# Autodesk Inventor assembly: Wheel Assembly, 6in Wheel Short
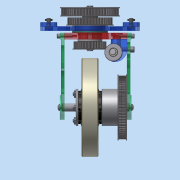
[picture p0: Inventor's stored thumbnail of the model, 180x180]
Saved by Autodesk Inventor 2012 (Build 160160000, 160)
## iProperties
Created: 2010-12
Part Number: Wheel Assembly, 6in Wheel Short
Document SubType Name: Assembly
Designer: PJ Suflita
Mass: 1486.61 g
Surface Area: 3664.62 cm^2
Volume: 597.184 cm^3
Density: 2.48936 g/cm^3
Author: PJ Suflita
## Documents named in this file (38)
- C:\Users\Owner\Documents\Robotics\Mechanical Design\DriveTrain2013 - post-season\Wheel Assembly\Inventor Parts\Wheel Assembly, 6in Wheel Short.iam
- C:\Users\Owner\Documents\Robotics\Mechanical Design\DriveTrain2013 - post-season\Wheel Assembly\Inventor Parts\SteeringRace_short.ipt
- C:\Users\Owner\Documents\Robotics\Mechanical Design\DriveTrain2013 - post-season\Wheel Assembly\Inventor Parts\ForkTopPlateLW.ipt
- C:\Users\Owner\Documents\Robotics\Mechanical Design\Parts\Bearings and Bushings\Thrust Bearings\Thrust Bearing, 1.500 in ID (INA TC2435).ipt
- C:\Users\Owner\Documents\Robotics\Mechanical Design\Parts\Bearings and Bushings\Thrust Bearings\Thrust Bearing Washer, 1.500 in ID (INA TWA2435).ipt
- C:\Users\Owner\Documents\Robotics\Mechanical Design\DriveTrain2013 - post-season\Wheel Assembly\Inventor Parts\AxleLWFinal.ipt
- C:\Users\Owner\Documents\Robotics\Mechanical Design\Parts\Wheels\2008-FIRST-Wheel\2008_FIRST-Wheel_Team174_Cleaned_up_version.iam
- C:\Users\Owner\Documents\Robotics\Mechanical Design\Parts\Fasteners\Retaining Rings (C-Clips)\Standard Retaining Ring, For 0.500 in Shaft (0.468 in Groove OD).ipt
- C:\Users\Owner\Documents\Robotics\Mechanical Design\Parts\Fasteners\Bolts and Screws\Socket Head Cap Screws - Buttonhead\SHCS (Buttonhead) - 1_4-20 UNC - UNC - 0.5(1).ipt
- C:\Users\Owner\Documents\Robotics\Mechanical Design\Parts\pulley\HTD\32\HTD 5mm 32 Tooth rev003 Assembly 001 step 4.iam
- C:\Users\Owner\Documents\Robotics\Mechanical Design\Parts\Bearings and Bushings\Roller Bearings\Roller Bearing, Flanged, 0.375 in ID.ipt
- C:\Users\Owner\Documents\Robotics\Mechanical Design\Parts\Fasteners\Shims\Washer, Spacer 0.375 in ID (0.020 in Thick).ipt
- C:\Users\Owner\Documents\Robotics\Mechanical Design\Parts\Fasteners\Retaining Rings (C-Clips)\Standard Retaining Ring, For 0.375 in Shaft (0.352 in Groove OD).ipt
- C:\Users\Owner\Documents\Robotics\Mechanical Design\Parts\Fasteners\Bolts and Screws\Socket Head Cap Screws\SHCS - 6-32 UNC - 0.5(31).ipt
- C:\Users\Owner\Documents\Robotics\Mechanical Design\Parts\Fasteners\Shims\Washer, Spacer 0.250 in ID (0.010 in Thick).ipt
- C:\Users\Owner\Documents\Robotics\Mechanical Design\Parts\Bearings and Bushings\Roller Bearings\Roller Bearing, Flanged, 0.250 in ID.ipt
- C:\Users\Owner\Documents\Robotics\Mechanical Design\Parts\pulley\HTD\16\HTD 5mm 16 Tooth rev001 Assembly.iam
- C:\Users\Owner\Documents\Robotics\Mechanical Design\DriveTrain2013 - post-season\Wheel Assembly\Inventor Parts\Customized Wheel Spacer.ipt
- C:\Users\Owner\Documents\Robotics\Mechanical Design\Parts\Bearings and Bushings\Roller Bearings\Roller Bearing, Flanged, 0.500 in ID.ipt
- C:\Users\Owner\Documents\Robotics\Mechanical Design\Parts\Fasteners\Shims\Washer, Spacer 0.500 in ID (0.020 in Thick).ipt
- C:\Users\Owner\Documents\Robotics\Mechanical Design\Parts\Fasteners\Bolts and Screws\Socket Head Cap Screws\SHCS - 10-32 UNF - 0.75(31).ipt
- C:\Users\Owner\Documents\Robotics\Mechanical Design\Parts\Fasteners\Bolts and Screws\Socket Head Cap Screws - Shoulder Bolt\SHCS, Shoulder, #10-32, 0.25 in Shoulder OD, 0.815 in Shoulder Length.ipt
- C:\Users\Owner\Documents\Robotics\Mechanical Design\Parts\pulley\HTD\56\HTD 5mm 56 Tooth Assembly rev003.iam
- C:\Users\Owner\Documents\Robotics\Mechanical Design\DriveTrain2013 - post-season\Wheel Assembly\Inventor Parts\Vertical Driven Shaft.ipt
- C:\Users\Owner\Documents\Robotics\Mechanical Design\Parts\pulley\HTD\44\HTD 5mm 44 Tooth rev001 Assembly 001.iam
- C:\Users\Owner\Documents\Robotics\Mechanical Design\Parts\pulley\HTD\9mm\Double Flange\62 Tooth\62 Tooth Complete Assembly.iam
- C:\Users\Owner\Documents\Robotics\Mechanical Design\Parts\Fasteners\Hexagon Nuts\Hex Nut, 8-32.ipt
- C:\Users\Owner\Documents\Robotics\Mechanical Design\DriveTrain2013 - post-season\Wheel Assembly\Inventor Parts\WheelWasher.ipt
- C:\Users\Owner\Documents\Robotics\Mechanical Design\Parts\Fasteners\Bolts and Screws\Socket Head Cap Screws\SHCS - 1_4-20 UNC - 0.75(31).ipt
- C:\Users\Owner\Documents\Robotics\Mechanical Design\Parts\8020 Hardware\8020 Single Slide-In Economy T-Nuts.ipt
- C:\Users\Owner\Documents\Robotics\Mechanical Design\DriveTrain2013 - post-season\Wheel Assembly\Inventor Parts\SteeringShaft_Short with Bushings.ipt
- C:\Users\Owner\Documents\Robotics\Mechanical Design\DriveTrain2013 - post-season\Wheel Assembly\Inventor Parts\FramePlateLW.ipt
- C:\Users\Owner\Documents\Robotics\Mechanical Design\Parts\Bearings and Bushings\Needle Bearings\Needle Bearing, 1.500 in ID (IKO BA248ZOH).ipt
- C:\Users\Owner\Documents\Robotics\Mechanical Design\DriveTrain2013 - post-season\Wheel Assembly\Inventor Parts\SideActiveFor6inWheel.ipt
- C:\Users\Owner\Documents\Robotics\Mechanical Design\DriveTrain2013 - post-season\Wheel Assembly\Inventor Parts\SidePassiveFor6inWheel.ipt
- C:\Users\Owner\Documents\Robotics\Mechanical Design\DriveTrain2013 - post-season\Wheel Assembly\Inventor Parts\Oblique Mount Block_Stationary_ForMachining.ipt
- C:\Users\Owner\Documents\Robotics\Mechanical Design\Parts\Fasteners\Bolts and Screws\Socket Head Cap Screws - Buttonhead\SHCS (Buttonhead) - 1_4-20 UNC - UNC - 0.75(1).ipt
- C:\Users\Owner\Documents\Inventor\Content Center Files\R2012\en-US\ANSI B18.3(05)\ANSI B18.3 - 8-32 UNC - 3(31).ipt
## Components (82 placed, 37 different names)
1. Washer, Spacer 0.375 in ID (0.020 in Thick):2 — Insert:118, Insert:155
2. HTD 5mm 56 Tooth Assembly rev003:2 [sub-assembly] — Insert:155, Angle:4
3. Roller Bearing, Flanged, 0.250 in ID:4 — Insert:126, Insert:127
4. HTD 5mm 44 Tooth rev001 Assembly 001:1 [sub-assembly] — Insert:159, Insert:163, Insert:179, Insert:180, Insert:194, Mate:177
5. Vertical Driven Shaft:1 — Insert:156, Insert:160, Insert:164
6. Standard Retaining Ring, For 0.375 in Shaft (0.352 in Groove OD):2 — Insert:164
7. 62 Tooth Complete Assembly:1 [sub-assembly] — Insert:165, Mate:165
8. Hex Machine Screw Nut - Inch 8 - 32:1 — Insert:175
9. Hex Machine Screw Nut - Inch 8 - 32:2 — Insert:176
10. Hex Machine Screw Nut - Inch 8 - 32:3 — Insert:177
11. Hex Machine Screw Nut - Inch 8 - 32:4 — Insert:178
12. Hex Machine Screw Nut - Inch 8 - 32:5 — Insert:173
13. Hex Machine Screw Nut - Inch 8 - 32:6 — Insert:174
14. WheelWasher:1 — Insert:172, Insert:173, Insert:174, Insert:175, Insert:176, Insert:177, Insert:178
15. Hexagon Socket Head Cap Screw - Inch No. 6 - 32 UNC - 1/2:1 — Insert:163
16. Hexagon Socket Head Cap Screw - Inch No. 6 - 32 UNC - 1/2:2 — Insert:179
17. Hexagon Socket Head Cap Screw - Inch No. 6 - 32 UNC - 1/2:3 — Insert:180
18. Hexagon Socket Head Cap Screw - Inch 1/4 - 20 UNC - 3/4:1 — Mate:171, Insert:202
19. Hexagon Socket Head Cap Screw - Inch 1/4 - 20 UNC - 3/4:2 — Mate:173, Insert:209
20. Washer, Spacer 0.500 in ID (0.020 in Thick):2 — Insert:184
21. Washer, Spacer 0.500 in ID (0.020 in Thick):3 — Insert:183
22. FramePlateLW:1 — Mate:176, Angle:5, Insert:185, Insert:186, Angle:6, Insert:187, Insert:188, Insert:189, Insert:190, Angle:7, Angle:8, Insert:191, Insert:192, Angle:9
23. 8020 Single Slide-In Economy T-Nuts:1 — Insert:186, Angle:6
24. 8020 Single Slide-In Economy T-Nuts:2 — Insert:192, Angle:9
25. 8020 Single Slide-In Economy T-Nuts:3 — Insert:189, Angle:8
26. 8020 Single Slide-In Economy T-Nuts:4 — Insert:190, Angle:7
27. Hexagon Socket Button Head Cap Screw - Inch 1/4 - 20 x 1/2:1 — Insert:187
28. Hexagon Socket Button Head Cap Screw - Inch 1/4 - 20 x 1/2:1 — Insert:188
29. Hexagon Socket Button Head Cap Screw - Inch 1/4 - 20 x 1/2:1 — Insert:191
30. Hexagon Socket Button Head Cap Screw - Inch 1/4 - 20 x 1/2:1 — Insert:185
31. Needle Bearing, 1.500 in ID (IKO BA248ZOH):1 — Insert:195, Insert:196
32. Oblique Mount Block_Stationary_ForMachining:1 — Insert:199, Insert:200, Mate:180, Mate:181, Mate:182
33. Hexagon Socket Button Head Cap Screw - Inch 1/4 - 20 x 3/4:1 — Mate:178, Mate:180, Mate:183
34. Hexagon Socket Button Head Cap Screw - Inch 1/4 - 20 x 3/4:2 — Mate:179, Mate:181, Mate:184
35. Hexagon Socket Head Cap Screw - Inch No. 8 - 32 UNC - 3:1
36. Hexagon Socket Head Cap Screw - Inch No. 8 - 32 UNC - 3:2
37. Hexagon Socket Head Cap Screw - Inch No. 8 - 32 UNC - 3:3
38. Hexagon Socket Head Cap Screw - Inch No. 8 - 32 UNC - 3:4
39. Hexagon Socket Head Cap Screw - Inch No. 8 - 32 UNC - 3:5
40. Hexagon Socket Head Cap Screw - Inch No. 8 - 32 UNC - 3:6
41. Hexagon Socket Head Cap Screw - Inch 10-32 UNF - 0.75:6 — Insert:142
42. Hexagon Socket Head Cap Screw - Inch 10-32 UNF - 0.75:5 — Insert:141
43. Hexagon Socket Head Cap Screw - Inch 10-32 UNF - 0.75:4 — Insert:140
44. Hexagon Socket Head Cap Screw - Inch 10-32 UNF - 0.75:3 — Insert:139
45. Hexagon Socket Head Cap Screw - Inch 10-32 UNF - 0.75:2 — Insert:138
46. Hexagon Socket Head Cap Screw - Inch 10-32 UNF - 0.75:1 — Insert:137
47. ForkTopPlateLW:1 — Mate:133, Insert:92, Insert:93, Mate:134, Insert:94, Insert:95, Angle:2, Mate:135, Insert:96, Insert:99, Insert:100, Mate:138, Mate:178, Mate:179, Mate:182, Mate:183, Mate:184
48. SidePassiveFor6inWheel:1 — Mate:133, Insert:92, Insert:93, Angle:3, Insert:106, Insert:140, Insert:141, Insert:142, Insert:144, Angle:5
49. SideActiveFor6inWheel:1 — Mate:134, Insert:94, Insert:95, Insert:134, Insert:137, Insert:138, Insert:139, Insert:143, Mate:171, Mate:173, Insert:202, Insert:209
50. Standard Retaining Ring, For 0.375 in Shaft (0.352 in Groove OD):1 — Insert:160
51. HTD 5mm 32 Tooth rev003 Assembly 001 step 4:1 [sub-assembly] — Insert:113, Insert:156
52. Roller Bearing, Flanged, 0.375 in ID:1 — Insert:111, Insert:112
53. Washer, Spacer 0.375 in ID (0.020 in Thick):1 — Insert:112, Insert:113
54. Roller Bearing, Flanged, 0.375 in ID:2 — Insert:118, Insert:159
55. SteeringShaft_Short with Bushings:1 — Mate:135, Insert:96, Insert:111, Insert:194, Mate:177
56. Thrust Bearing, 1.500 in ID (INA TC2435):1 — Insert:97, Insert:98
57. Thrust Bearing Washer, 1.500 in ID (INA TWA2435):1 — Insert:97, Insert:99
58. Thrust Bearing Washer, 1.500 in ID (INA TWA2435):2 — Insert:98, Flush:1, Mate:176, Insert:195
59. SteeringRace_short:1 — Insert:100
60. Thrust Bearing Washer, 1.500 in ID (INA TWA2435):3 — Insert:102, Insert:196
61. Thrust Bearing, 1.500 in ID (INA TC2435):2 — Insert:102, Insert:103
62. Thrust Bearing Washer, 1.500 in ID (INA TWA2435):4 — Insert:103
63. Hexagon Socket Button Head Cap Screw - Inch 1/4 - 20 x 1/2:3 — Insert:143
64. Hexagon Socket Button Head Cap Screw - Inch 1/4 - 20 x 1/2:4 — Insert:144
65. Roller Bearing, Flanged, 0.500 in ID:1 — Insert:133, Insert:165
66. Washer, Spacer 0.500 in ID (0.020 in Thick):1 — Insert:133, Insert:134
67. Customized Wheel Spacer:1 — Insert:128, Insert:129, Mate:164, Mate:165
68. AxleLWFinal:1 — Insert:106, Mate:137, Insert:109, Insert:110
69. 2008_FIRST-Wheel_Team174_Cleaned_up_version:1 [sub-assembly] — Mate:137, Mate:138, Insert:128, Insert:129, Mate:164, Insert:172, Insert:183, Insert:184
70. Standard Retaining Ring, For 0.500 in Shaft (0.468 in Groove OD):1 — Insert:110
71. Standard Retaining Ring, For 0.500 in Shaft (0.468 in Groove OD):2 — Insert:109
72. SHCS, Shoulder, #10-32, 0.25 in Shoulder OD, 0.815 in Shoulder Length:1 — Mate:161, Insert:146
73. SHCS, Shoulder, #10-32, 0.25 in Shoulder OD, 0.815 in Shoulder Length:2 — Mate:163, Insert:148
74. Washer, Spacer 0.250 in ID (0.010 in Thick):3 — Insert:145, Insert:146
75. Washer, Spacer 0.250 in ID (0.010 in Thick):4 — Insert:147, Insert:148
76. Washer, Spacer 0.250 in ID (0.010 in Thick):1 — Insert:124, Insert:199
77. Washer, Spacer 0.250 in ID (0.010 in Thick):2 — Insert:127, Insert:200
78. Roller Bearing, Flanged, 0.250 in ID:1 — Insert:122, Mate:161, Insert:145
79. HTD 5mm 16 Tooth rev001 Assembly:1 [sub-assembly] — Insert:122, Insert:123
80. Roller Bearing, Flanged, 0.250 in ID:2 — Insert:123, Insert:124
81. Roller Bearing, Flanged, 0.250 in ID:3 — Insert:125, Mate:163, Insert:147
82. HTD 5mm 16 Tooth rev001 Assembly:2 [sub-assembly] — Insert:125, Insert:126
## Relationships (102: Insert 73, Mate 20, Angle 8, Flush 1)
- Mate:133: ForkTopPlateLW:1 ↔ SidePassiveFor6inWheel:1
- Insert:92: ForkTopPlateLW:1 ↔ SidePassiveFor6inWheel:1
- Insert:93: ForkTopPlateLW:1 ↔ SidePassiveFor6inWheel:1
- Mate:134: ForkTopPlateLW:1 ↔ SideActiveFor6inWheel:1
- Insert:94: ForkTopPlateLW:1 ↔ SideActiveFor6inWheel:1
- Insert:95: ForkTopPlateLW:1 ↔ SideActiveFor6inWheel:1
- Angle:2: ForkTopPlateLW:1
- Angle:3: SidePassiveFor6inWheel:1
- Mate:135: ForkTopPlateLW:1 ↔ SteeringShaft_Short with Bushings:1
- Insert:96: ForkTopPlateLW:1 ↔ SteeringShaft_Short with Bushings:1
- Insert:97: Thrust Bearing, 1.500 in ID (INA TC2435):1 ↔ Thrust Bearing Washer, 1.500 in ID (INA TWA2435):1
- Insert:98: Thrust Bearing, 1.500 in ID (INA TC2435):1 ↔ Thrust Bearing Washer, 1.500 in ID (INA TWA2435):2
- Insert:99: ForkTopPlateLW:1 ↔ Thrust Bearing Washer, 1.500 in ID (INA TWA2435):1
- Insert:100: ForkTopPlateLW:1 ↔ SteeringRace_short:1
- Insert:102: Thrust Bearing Washer, 1.500 in ID (INA TWA2435):3 ↔ Thrust Bearing, 1.500 in ID (INA TC2435):2
- Insert:103: Thrust Bearing, 1.500 in ID (INA TC2435):2 ↔ Thrust Bearing Washer, 1.500 in ID (INA TWA2435):4
- Insert:106: SidePassiveFor6inWheel:1 ↔ AxleLWFinal:1
- Mate:137: AxleLWFinal:1 ↔ 2008_FIRST-Wheel_Team174_Cleaned_up_version:1
- Mate:138: ForkTopPlateLW:1 ↔ 2008_FIRST-Wheel_Team174_Cleaned_up_version:1
- Insert:109: AxleLWFinal:1 ↔ Standard Retaining Ring, For 0.500 in Shaft (0.468 in Groove OD):2
- Insert:110: AxleLWFinal:1 ↔ Standard Retaining Ring, For 0.500 in Shaft (0.468 in Groove OD):1
- Insert:111: Roller Bearing, Flanged, 0.375 in ID:1 ↔ SteeringShaft_Short with Bushings:1
- Insert:112: Roller Bearing, Flanged, 0.375 in ID:1 ↔ Washer, Spacer 0.375 in ID (0.020 in Thick):1
- Insert:113: HTD 5mm 32 Tooth rev003 Assembly 001 step 4:1 ↔ Washer, Spacer 0.375 in ID (0.020 in Thick):1
- Insert:118: Washer, Spacer 0.375 in ID (0.020 in Thick):2 ↔ Roller Bearing, Flanged, 0.375 in ID:2
- Insert:122: Roller Bearing, Flanged, 0.250 in ID:1 ↔ HTD 5mm 16 Tooth rev001 Assembly:1
- Insert:123: HTD 5mm 16 Tooth rev001 Assembly:1 ↔ Roller Bearing, Flanged, 0.250 in ID:2
- Insert:124: Washer, Spacer 0.250 in ID (0.010 in Thick):1 ↔ Roller Bearing, Flanged, 0.250 in ID:2
- Insert:125: Roller Bearing, Flanged, 0.250 in ID:3 ↔ HTD 5mm 16 Tooth rev001 Assembly:2
- Insert:126: Roller Bearing, Flanged, 0.250 in ID:4 ↔ HTD 5mm 16 Tooth rev001 Assembly:2
- Insert:127: Roller Bearing, Flanged, 0.250 in ID:4 ↔ Washer, Spacer 0.250 in ID (0.010 in Thick):2
- Insert:128: Customized Wheel Spacer:1 ↔ 2008_FIRST-Wheel_Team174_Cleaned_up_version:1
- Insert:129: Customized Wheel Spacer:1 ↔ 2008_FIRST-Wheel_Team174_Cleaned_up_version:1
- Insert:133: Roller Bearing, Flanged, 0.500 in ID:1 ↔ Washer, Spacer 0.500 in ID (0.020 in Thick):1
- Insert:134: SideActiveFor6inWheel:1 ↔ Washer, Spacer 0.500 in ID (0.020 in Thick):1
- Flush:1: Thrust Bearing Washer, 1.500 in ID (INA TWA2435):2
- Insert:137: Hexagon Socket Head Cap Screw - Inch 10-32 UNF - 0.75:1 ↔ SideActiveFor6inWheel:1
- Insert:138: Hexagon Socket Head Cap Screw - Inch 10-32 UNF - 0.75:2 ↔ SideActiveFor6inWheel:1
- Insert:139: Hexagon Socket Head Cap Screw - Inch 10-32 UNF - 0.75:3 ↔ SideActiveFor6inWheel:1
- Insert:140: Hexagon Socket Head Cap Screw - Inch 10-32 UNF - 0.75:4 ↔ SidePassiveFor6inWheel:1
- Insert:141: Hexagon Socket Head Cap Screw - Inch 10-32 UNF - 0.75:5 ↔ SidePassiveFor6inWheel:1
- Insert:142: Hexagon Socket Head Cap Screw - Inch 10-32 UNF - 0.75:6 ↔ SidePassiveFor6inWheel:1
- Insert:143: SideActiveFor6inWheel:1 ↔ Hexagon Socket Button Head Cap Screw - Inch 1/4 - 20 x 1/2:3
- Insert:144: SidePassiveFor6inWheel:1 ↔ Hexagon Socket Button Head Cap Screw - Inch 1/4 - 20 x 1/2:4
- Mate:161: SHCS, Shoulder, #10-32, 0.25 in Shoulder OD, 0.815 in Shoulder Length:1 ↔ Roller Bearing, Flanged, 0.250 in ID:1
- Mate:163: SHCS, Shoulder, #10-32, 0.25 in Shoulder OD, 0.815 in Shoulder Length:2 ↔ Roller Bearing, Flanged, 0.250 in ID:3
- Insert:145: Washer, Spacer 0.250 in ID (0.010 in Thick):3 ↔ Roller Bearing, Flanged, 0.250 in ID:1
- Insert:146: SHCS, Shoulder, #10-32, 0.25 in Shoulder OD, 0.815 in Shoulder Length:1 ↔ Washer, Spacer 0.250 in ID (0.010 in Thick):3
- Insert:147: Washer, Spacer 0.250 in ID (0.010 in Thick):4 ↔ Roller Bearing, Flanged, 0.250 in ID:3
- Insert:148: SHCS, Shoulder, #10-32, 0.25 in Shoulder OD, 0.815 in Shoulder Length:2 ↔ Washer, Spacer 0.250 in ID (0.010 in Thick):4
- Insert:155: Washer, Spacer 0.375 in ID (0.020 in Thick):2 ↔ HTD 5mm 56 Tooth Assembly rev003:2
- Insert:156: Vertical Driven Shaft:1 ↔ HTD 5mm 32 Tooth rev003 Assembly 001 step 4:1
- Insert:159: HTD 5mm 44 Tooth rev001 Assembly 001:1 ↔ Roller Bearing, Flanged, 0.375 in ID:2
- Insert:160: Vertical Driven Shaft:1 ↔ Standard Retaining Ring, For 0.375 in Shaft (0.352 in Groove OD):1
- Insert:163: HTD 5mm 44 Tooth rev001 Assembly 001:1 ↔ Hexagon Socket Head Cap Screw - Inch No. 6 - 32 UNC - 1/2:1
- Angle:4: HTD 5mm 56 Tooth Assembly rev003:2
- Insert:164: Vertical Driven Shaft:1 ↔ Standard Retaining Ring, For 0.375 in Shaft (0.352 in Groove OD):2
- Mate:164: Customized Wheel Spacer:1 ↔ 2008_FIRST-Wheel_Team174_Cleaned_up_version:1
- Insert:165: 62 Tooth Complete Assembly:1 ↔ Roller Bearing, Flanged, 0.500 in ID:1
- Mate:165: 62 Tooth Complete Assembly:1 ↔ Customized Wheel Spacer:1
- Insert:172: WheelWasher:1 ↔ 2008_FIRST-Wheel_Team174_Cleaned_up_version:1
- Insert:173: Hex Machine Screw Nut - Inch 8 - 32:5 ↔ WheelWasher:1
- Insert:174: Hex Machine Screw Nut - Inch 8 - 32:6 ↔ WheelWasher:1
- Insert:175: Hex Machine Screw Nut - Inch 8 - 32:1 ↔ WheelWasher:1
- Insert:176: Hex Machine Screw Nut - Inch 8 - 32:2 ↔ WheelWasher:1
- Insert:177: Hex Machine Screw Nut - Inch 8 - 32:3 ↔ WheelWasher:1
- Insert:178: Hex Machine Screw Nut - Inch 8 - 32:4 ↔ WheelWasher:1
- Insert:179: HTD 5mm 44 Tooth rev001 Assembly 001:1 ↔ Hexagon Socket Head Cap Screw - Inch No. 6 - 32 UNC - 1/2:2
- Insert:180: HTD 5mm 44 Tooth rev001 Assembly 001:1 ↔ Hexagon Socket Head Cap Screw - Inch No. 6 - 32 UNC - 1/2:3
- Mate:171: Hexagon Socket Head Cap Screw - Inch 1/4 - 20 UNC - 3/4:1 ↔ SideActiveFor6inWheel:1
- Mate:173: Hexagon Socket Head Cap Screw - Inch 1/4 - 20 UNC - 3/4:2 ↔ SideActiveFor6inWheel:1
- Insert:183: Washer, Spacer 0.500 in ID (0.020 in Thick):3 ↔ 2008_FIRST-Wheel_Team174_Cleaned_up_version:1
- Insert:184: Washer, Spacer 0.500 in ID (0.020 in Thick):2 ↔ 2008_FIRST-Wheel_Team174_Cleaned_up_version:1
- Mate:176: FramePlateLW:1 ↔ Thrust Bearing Washer, 1.500 in ID (INA TWA2435):2
- Angle:5: FramePlateLW:1 ↔ SidePassiveFor6inWheel:1
- Insert:185: FramePlateLW:1 ↔ Hexagon Socket Button Head Cap Screw - Inch 1/4 - 20 x 1/2:1
- Insert:186: FramePlateLW:1 ↔ 8020 Single Slide-In Economy T-Nuts:1
- Angle:6: FramePlateLW:1 ↔ 8020 Single Slide-In Economy T-Nuts:1
- Insert:187: FramePlateLW:1 ↔ Hexagon Socket Button Head Cap Screw - Inch 1/4 - 20 x 1/2:1
- Insert:188: FramePlateLW:1 ↔ Hexagon Socket Button Head Cap Screw - Inch 1/4 - 20 x 1/2:1
- Insert:189: FramePlateLW:1 ↔ 8020 Single Slide-In Economy T-Nuts:3
- Insert:190: FramePlateLW:1 ↔ 8020 Single Slide-In Economy T-Nuts:4
- Angle:7: FramePlateLW:1 ↔ 8020 Single Slide-In Economy T-Nuts:4
- Angle:8: FramePlateLW:1 ↔ 8020 Single Slide-In Economy T-Nuts:3
- Insert:191: FramePlateLW:1 ↔ Hexagon Socket Button Head Cap Screw - Inch 1/4 - 20 x 1/2:1
- Insert:192: FramePlateLW:1 ↔ 8020 Single Slide-In Economy T-Nuts:2
- Angle:9: FramePlateLW:1 ↔ 8020 Single Slide-In Economy T-Nuts:2
- Insert:194: HTD 5mm 44 Tooth rev001 Assembly 001:1 ↔ SteeringShaft_Short with Bushings:1
- Mate:177: HTD 5mm 44 Tooth rev001 Assembly 001:1 ↔ SteeringShaft_Short with Bushings:1
- Insert:195: Needle Bearing, 1.500 in ID (IKO BA248ZOH):1 ↔ Thrust Bearing Washer, 1.500 in ID (INA TWA2435):2
- Insert:196: Needle Bearing, 1.500 in ID (IKO BA248ZOH):1 ↔ Thrust Bearing Washer, 1.500 in ID (INA TWA2435):3
- Insert:199: Oblique Mount Block_Stationary_ForMachining:1 ↔ Washer, Spacer 0.250 in ID (0.010 in Thick):1
- Insert:200: Oblique Mount Block_Stationary_ForMachining:1 ↔ Washer, Spacer 0.250 in ID (0.010 in Thick):2
- Mate:178: Hexagon Socket Button Head Cap Screw - Inch 1/4 - 20 x 3/4:1 ↔ ForkTopPlateLW:1
- Mate:179: Hexagon Socket Button Head Cap Screw - Inch 1/4 - 20 x 3/4:2 ↔ ForkTopPlateLW:1
- Mate:180: Oblique Mount Block_Stationary_ForMachining:1 ↔ Hexagon Socket Button Head Cap Screw - Inch 1/4 - 20 x 3/4:1
- Mate:181: Oblique Mount Block_Stationary_ForMachining:1 ↔ Hexagon Socket Button Head Cap Screw - Inch 1/4 - 20 x 3/4:2
- Mate:182: Oblique Mount Block_Stationary_ForMachining:1 ↔ ForkTopPlateLW:1
- Mate:183: Hexagon Socket Button Head Cap Screw - Inch 1/4 - 20 x 3/4:1 ↔ ForkTopPlateLW:1
- Mate:184: Hexagon Socket Button Head Cap Screw - Inch 1/4 - 20 x 3/4:2 ↔ ForkTopPlateLW:1
- Insert:202: Hexagon Socket Head Cap Screw - Inch 1/4 - 20 UNC - 3/4:1 ↔ SideActiveFor6inWheel:1
- Insert:209: Hexagon Socket Head Cap Screw - Inch 1/4 - 20 UNC - 3/4:2 ↔ SideActiveFor6inWheel:1
